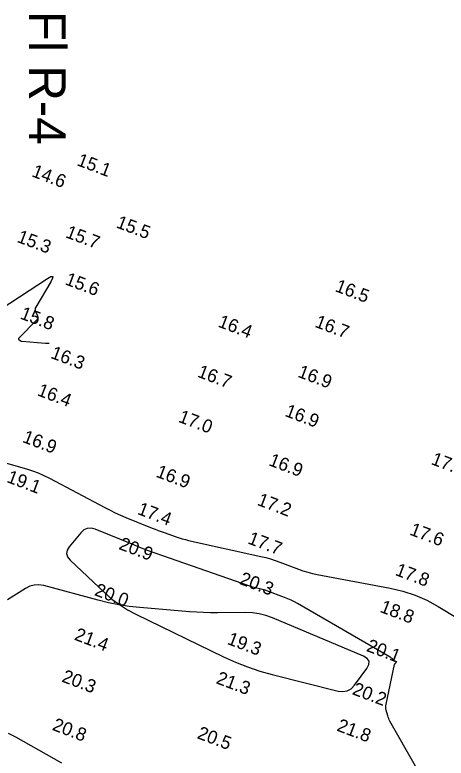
# Model space of a CAD drawing. Extents: x 824616 to 827440, y 158441 to 163197.
# Drawn here: x 826928.3 to 827092.4, y 159873.5 to 160156.5 of the extents above; entities that cross this region are included whole.
import ezdxf

# ---------------------------------------------------------------- set-up
doc = ezdxf.new("R2010")
doc.units = 0
for name, color, linetype in [('V-CHAN-CONT-EL16', 7, 'Continuous'), ('V-CHAN-CONT-EL18', 7, 'Continuous'), ('V-CHAN-CONT-EL20', 7, 'Continuous'), ('V-CHAN-NAID', 7, 'Continuous'), ('V-TOPO-SOUN', 7, 'Continuous')]:
    doc.layers.add(name, color=color, linetype=linetype)

msp = doc.modelspace()

# ---------------------------------------------------------------- linework, layer by layer
at = {"layer": 'V-CHAN-CONT-EL16'}
msp.add_lwpolyline([(826915.6, 160039.83), (826940.61, 160056.12), (826941.96, 160056.87), (826942.64, 160056.91), (826942.63, 160056.24), (826941.93, 160054.85), (826936.19, 160045.21), (826936.01, 160044.81), (826935.93, 160044.4), (826935.96, 160043.98), (826936.1, 160043.56), (826936.86, 160041.87), (826936.99, 160041.45), (826936.98, 160041.07), (826936.85, 160040.7), (826936.59, 160040.36), (826929.74, 160033.44), (826929.65, 160033.31), (826929.62, 160033.19), (826929.66, 160033.08), (826929.75, 160032.96), (826930.27, 160032.5), (826930.41, 160032.4), (826930.56, 160032.33), (826930.71, 160032.27), (826930.88, 160032.25), (826939.94, 160031.53), (826941.3, 160031.48)], dxfattribs=at)
at = {"layer": 'V-CHAN-CONT-EL18'}
msp.add_lwpolyline([(826923.27, 159986.29), (826932.65, 159983.66), (826934.91, 159982.96), (826937.13, 159982.14), (826939.31, 159981.2), (826941.43, 159980.14), (826962.52, 159968.92), (826964.48, 159967.91), (826966.46, 159966.95), (826968.46, 159966.04), (826970.49, 159965.18), (826980.45, 159961.11), (826981.59, 159960.66), (826982.73, 159960.22), (826983.87, 159959.79), (826985.02, 159959.38), (826989.65, 159957.77), (826990.81, 159957.39), (826991.97, 159957.04), (826993.15, 159956.72), (826994.34, 159956.44), (827021.89, 159950.3), (827023.71, 159949.86), (827025.52, 159949.36), (827027.31, 159948.79), (827029.08, 159948.15), (827036.12, 159945.49), (827037.89, 159944.86), (827039.68, 159944.32), (827041.5, 159943.85), (827043.34, 159943.46), (827071.02, 159938.28), (827075.85, 159937.15), (827080.52, 159935.61), (827085.03, 159933.64), (827089.38, 159931.26), (827111.36, 159917.94)], dxfattribs=at)
at = {"layer": 'V-CHAN-CONT-EL20'}
for points in [[(827080.7, 159870.45), (827070.98, 159887.58), (827070.72, 159888.08), (827070.5, 159888.59), (827070.3, 159889.11), (827070.14, 159889.65), (827069.58, 159891.83), (827069.47, 159892.38), (827069.42, 159892.92), (827069.44, 159893.47), (827069.53, 159894.02), (827072.76, 159909.15), (827072.79, 159909.25), (827072.83, 159909.35), (827072.89, 159909.44), (827072.96, 159909.52), (827073.27, 159909.84), (827073.33, 159909.92), (827073.35, 159910), (827073.32, 159910.07), (827073.26, 159910.15), (827072.02, 159911.26), (827071.78, 159911.46), (827071.53, 159911.65), (827071.27, 159911.83), (827071, 159911.99), (827035.8, 159932.36), (827034.6, 159933.03), (827033.37, 159933.64), (827032.11, 159934.21), (827030.83, 159934.72), (827024.14, 159937.26), (827023.61, 159937.45), (827023.08, 159937.62), (827022.54, 159937.77), (827021.99, 159937.9), (827019.8, 159938.39), (827019.26, 159938.52), (827018.72, 159938.66), (827018.18, 159938.82), (827017.65, 159939), (826984.55, 159950.52), (826981.62, 159951.56), (826978.69, 159952.64), (826975.78, 159953.77), (826972.89, 159954.93), (826958.77, 159960.69), (826957.23, 159961.1), (826955.82, 159961.01), (826954.52, 159960.42), (826953.36, 159959.33), (826948.94, 159953.98), (826948.13, 159952.67), (826947.92, 159951.39), (826948.29, 159950.14), (826949.26, 159948.93), (826962.5, 159936.46), (826965.2, 159934.1), (826968.06, 159931.96), (826971.07, 159930.04), (826974.24, 159928.35), (827007.67, 159912.1), (827012.17, 159910.05), (827016.77, 159908.24), (827021.45, 159906.68), (827026.22, 159905.35), (827051.27, 159899.08), (827053.1, 159898.85), (827054.74, 159899.15), (827056.2, 159899.97), (827057.47, 159901.3), (827062.17, 159907.67), (827062.97, 159909.16), (827063.02, 159910.44), (827062.32, 159911.52), (827060.87, 159912.39), (827026.23, 159926.95), (827023.75, 159927.85), (827021.22, 159928.49), (827018.63, 159928.86), (827016, 159928.96), (827005.35, 159928.86), (827002.69, 159928.87), (827000.03, 159928.93), (826997.37, 159929.06), (826994.72, 159929.25), (826975.82, 159930.84), (826971.8, 159931.26), (826967.81, 159931.87), (826963.86, 159932.65), (826959.93, 159933.62), (826939.25, 159939.2), (826937.41, 159939.51), (826935.64, 159939.44), (826933.92, 159938.98), (826932.26, 159938.14), (826925.45, 159933.81)], [(826925.74, 159883.09), (826928.5, 159881.59), (826946.03, 159871.75)]]:
    msp.add_lwpolyline(points, dxfattribs=at)

# ---------------------------------------------------------------- texts
at = {"layer": 'V-CHAN-NAID'}
msp.add_text('Fl R-4', height=14, rotation=270, dxfattribs=at).set_placement((826933.62, 160158.05))
at = {"layer": 'V-TOPO-SOUN'}
for s, p in [('15.1 ', (826951.55, 160099.33)), ('14.6 ', (826934.35, 160095.12)), ('15.5 ', (826966.49, 160075.66)), ('15.7 ', (826947.23, 160071.91)), ('15.3 ', (826928.73, 160070.15)), ('15.6 ', (826947.04, 160053.99)), ('16.5 ', (827049.78, 160051.39)), ('15.8 ', (826929.92, 160040.97)), ('16.4 ', (827005.24, 160037.88)), ('16.7 ', (827042.11, 160037.8)), ('16.3 ', (826941.55, 160025.97)), ('16.7 ', (826997.38, 160018.82)), ('16.9 ', (827035.57, 160018.78)), ('16.4 ', (826936.46, 160011.74)), ('16.9 ', (827030.69, 160003.86)), ('17.0 ', (826990.14, 160001.65)), ('16.9 ', (826930.83, 159993.96)), ('16.9 ', (827024.53, 159985.12)), ('17.2 ', (827086.33, 159985.54)), ('19.1 ', (826924.84, 159978.72)), ('16.9 ', (826981.63, 159980.74)), ('17.2 ', (827020.16, 159970)), ('17.4 ', (826974.58, 159966.54)), ('17.6 ', (827078.16, 159958.7)), ('17.7 ', (827016.59, 159955.33)), ('20.9 ', (826967.5, 159953.21)), ('17.8 ', (827072.66, 159943.32)), ('20.3 ', (827013.38, 159939.95)), ('20.0 ', (826958.22, 159935.65)), ('18.8 ', (827066.85, 159929.28)), ('21.4 ', (826950.57, 159918.7)), ('19.3 ', (827008.72, 159917.07)), ('20.1 ', (827061.71, 159914.4)), ('20.3 ', (826945.78, 159902.75)), ('21.3 ', (827004.53, 159902.1)), ('20.2 ', (827056.33, 159897.93)), ('20.8 ', (826942.17, 159884.35)), ('21.8 ', (827050.44, 159884.07)), ('20.5 ', (826997.31, 159881.18))]:
    msp.add_text(s, height=5, rotation=339.2, dxfattribs=at).set_placement(p)

doc.saveas('drawing.dxf')
